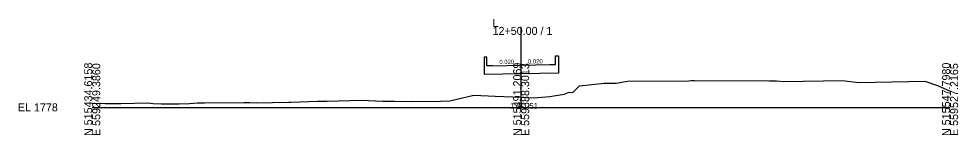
# Model space of a CAD drawing. Extents: x -26 to 1303, y -10 to 9545.
# Drawn here: x -25.7 to 302.8, y 6490.3 to 6530.9 of the extents above; entities that cross this region are included whole.
import ezdxf

# ---------------------------------------------------------------- set-up
doc = ezdxf.new("R2010")
doc.units = 0
for name, color, linetype in [('Exist Cross Section Cell', 7, 'Continuous'), ('Exist XS Center Line Elevation Label', 7, 'Continuous'), ('Exist XS Ground Line', 7, 'Continuous'), ('Prop XS Bridge', 7, 'Continuous'), ('Prop XS Dump Level', 7, 'Continuous'), ('Prop XS SE Text', 7, 'Continuous')]:
    doc.layers.add(name, color=color, linetype=linetype)

msp = doc.modelspace()

# ---------------------------------------------------------------- linework, layer by layer
at = {"layer": 'Exist Cross Section Cell'}
for p, q in [((150, 6500), (150, 6528.08)), ((0, 6500), (150, 6500)), ((150, 6500), (300, 6500))]:
    msp.add_line(p, q, dxfattribs=at)
at = {"layer": 'Exist XS Ground Line'}
for p, q in [((170.35, 6507.57), (179.03, 6508.49)), ((179.03, 6508.49), (183.22, 6508.46)), ((183.22, 6508.46), (186.52, 6509.06)), ((186.52, 6509.06), (188.02, 6509.27)), ((188.02, 6509.27), (207.32, 6509.19)), ((207.32, 6509.19), (208.58, 6509.28)), ((208.58, 6509.28), (209.4, 6509.32)), ((209.4, 6509.32), (210.57, 6509.34)), ((210.57, 6509.34), (236.9, 6509.26)), ((236.9, 6509.26), (238.21, 6509.24)), ((238.21, 6509.24), (239.33, 6509.2)), ((239.33, 6509.2), (241.7, 6509.06)), ((241.7, 6509.06), (262.54, 6509.36)), ((262.54, 6509.36), (264.17, 6509.19)), ((264.17, 6509.19), (268.26, 6508.7)), ((268.26, 6508.7), (291.21, 6509.11)), ((291.21, 6509.11), (295.58, 6507.62)), ((165.07, 6504.61), (166.78, 6505.25)), ((166.78, 6505.25), (168.09, 6505.24)), ((168.09, 6505.24), (168.66, 6505.79)), ((168.66, 6505.79), (170.35, 6507.57)), ((295.58, 6507.62), (300, 6505.69)), ((39.3, 6501.54), (53.04, 6501.67)), ((53.04, 6501.67), (55.06, 6501.68)), ((55.06, 6501.68), (57.36, 6501.54)), ((57.36, 6501.54), (68.76, 6501.8)), ((68.76, 6501.8), (69.48, 6501.82)), ((69.48, 6501.82), (78.91, 6502.16)), ((78.91, 6502.16), (82.14, 6502.21)), ((82.14, 6502.21), (94.08, 6502.56)), ((94.08, 6502.56), (101.66, 6502.19)), ((101.66, 6502.19), (103.52, 6502.2)), ((103.52, 6502.2), (104.84, 6502.21)), ((104.84, 6502.21), (105.58, 6502.18)), ((105.58, 6502.18), (112.06, 6502.04)), ((112.06, 6502.04), (121.75, 6502.21)), ((121.75, 6502.21), (125.01, 6502.3)), ((125.01, 6502.3), (133.45, 6504.3)), ((133.45, 6504.3), (140.85, 6503.95)), ((140.85, 6503.95), (150, 6503.51)), ((150, 6503.51), (154.44, 6503.3)), ((154.44, 6503.3), (159.99, 6503.82)), ((159.99, 6503.82), (165.07, 6504.61)), ((0, 6501.47), (4.51, 6501.35)), ((4.51, 6501.35), (10.01, 6501.37)), ((10.01, 6501.37), (19.48, 6501.54)), ((19.48, 6501.54), (21.26, 6501.39)), ((21.26, 6501.39), (24.26, 6501.21)), ((24.26, 6501.21), (30.38, 6501.28)), ((30.38, 6501.28), (33.99, 6501.32)), ((33.99, 6501.32), (36.86, 6501.55)), ((36.86, 6501.55), (39.3, 6501.54))]:
    msp.add_line(p, q, dxfattribs=at)
at = {"layer": 'Prop XS Bridge'}
for p, q in [((137, 6517.48), (137, 6514.48)), ((138, 6517.48), (137, 6517.48)), ((138, 6514.48), (138, 6517.48)), ((150, 6514.72), (160, 6514.92)), ((160, 6514.92), (162, 6514.96)), ((162, 6514.96), (162, 6517.96)), ((162, 6517.96), (163, 6517.96)), ((163, 6517.96), (163, 6514.96)), ((163, 6514.96), (163, 6511.96)), ((137, 6514.48), (137, 6511.48)), ((163, 6511.96), (137, 6511.48)), ((140, 6514.52), (138, 6514.48)), ((140, 6514.52), (150, 6514.72))]:
    msp.add_line(p, q, dxfattribs=at)
at = {"layer": 'Prop XS Dump Level'}
for p, q in [((150, 6514.72), (160, 6514.92)), ((140, 6514.52), (150, 6514.72))]:
    msp.add_line(p, q, dxfattribs=at)

# ---------------------------------------------------------------- texts
at = {"layer": 'Exist Cross Section Cell'}
for s, p in [('12+50.00 / 1', (140, 6525.28)), ('L', (140, 6528.08)), ('EL 1778', (-26, 6498.6))]:
    msp.add_text(s, height=2.8, dxfattribs=at).set_placement(p)
for s, p in [('N 515434.6158', (0, 6490)), ('E 559249.3860', (2.8, 6490)), ('N 515491.2069', (150, 6490)), ('E 559388.3013', (152.8, 6490)), ('N 515547.7980', (300, 6490)), ('E 559527.2165', (302.8, 6490))]:
    msp.add_text(s, height=2.8, rotation=90, dxfattribs=at).set_placement(p)
at = {"layer": 'Exist XS Center Line Elevation Label'}
msp.add_text('1781.51', height=2, dxfattribs=at).set_placement((146.16, 6499.51))
at = {"layer": 'Prop XS SE Text'}
for p in [(142.38, 6515.07), (152.38, 6515.27)]:
    msp.add_text('0.020', height=1.5, rotation=1.1458, dxfattribs=at).set_placement(p)

doc.saveas('drawing.dxf')
